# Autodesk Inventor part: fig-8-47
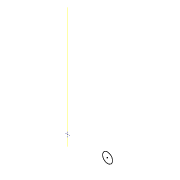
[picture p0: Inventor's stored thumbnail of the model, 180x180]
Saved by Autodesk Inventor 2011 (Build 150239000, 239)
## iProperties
Shininess: 77.0
Length Units: 11269
Angle Units: 11279
Time Units: 11290
Mass Units: 11283
Length Display Precision: 3
Angle Display Precision: 2
Created: 2002-01
Part Number: fig-8-47
Document SubType Name: Modeling
Designer: CADSoft
Density: 1 g/cm^3
Density: 0.0
Volumn: 0.0
Area: 0.0
PropertySet Name: Model Information
Control State: 0
Master: False
Checked Out: False
Author: CADSoft
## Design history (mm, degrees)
sketch "Sketch2"
  geometry: C1 r 2.5 at (-20, -0.092); 1 further point
  constraints: 1 centre point, 2 other
workaxis "Work Axis1"
body "Solid1"
